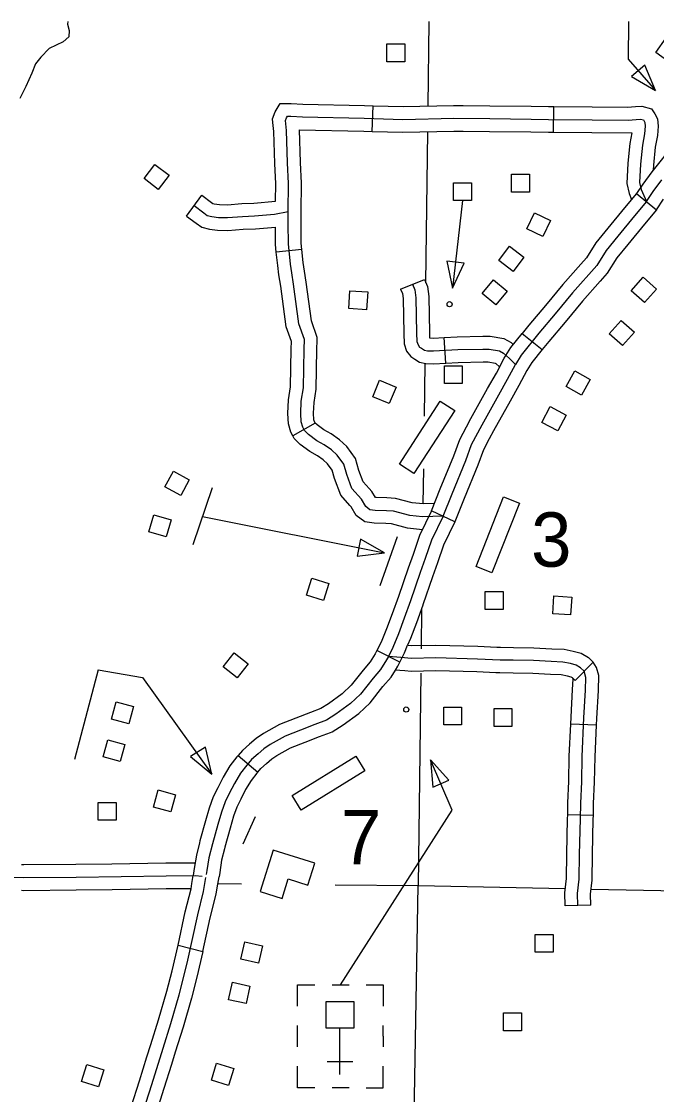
# Model space of a CAD drawing. Extents: x 61396 to 64680, y 55472 to 57605.
# Drawn here: x 63205.3 to 63321.1, y 56489.6 to 56685.3 of the extents above; entities that cross this region are included whole.
import ezdxf

# ---------------------------------------------------------------- set-up
doc = ezdxf.new("R2010")
doc.units = 0
for name, color, linetype in [('31', 7, 'Continuous'), ('32', 7, 'Continuous'), ('35', 7, 'Continuous'), ('45', 7, 'Continuous'), ('5', 7, 'Continuous'), ('56', 7, 'Continuous'), ('57', 7, 'Continuous'), ('58', 7, 'Continuous')]:
    doc.layers.add(name, color=color, linetype=linetype)

msp = doc.modelspace()

# ---------------------------------------------------------------- linework, layer by layer
at = {"layer": '31'}
for p, q in [((63317.45, 56653.93), (63321.06, 56650.95)), ((63296.58, 56628.37), (63300.23, 56625.43)), ((63284.29, 56594.04), (63280.07, 56596.07)), ((63274.29, 56568.45), (63270.1, 56570.55)), ((63309.55, 56568.45), (63306.23, 56565.13)), ((63244.8, 56551.46), (63248.37, 56548.42)), ((63233.85, 56516.86), (63238.39, 56515.68))]:
    msp.add_line(p, q, dxfattribs=at)
for points in [[(63324.79, 56663.59), (63324.33, 56662.98), (63320.26, 56657.86)], [(63320.26, 56657.86), (63318.6, 56655.63), (63317.45, 56653.93)], [(63319.26, 56652.44), (63320.51, 56654.27), (63322.09, 56656.4)], [(63317.45, 56653.93), (63315.28, 56651.3), (63312.22, 56647.59), (63310.02, 56644.91), (63308.33, 56642.19), (63307.31, 56641.04)], [(63319.26, 56652.44), (63317.09, 56649.81), (63314.03, 56646.1), (63311.93, 56643.54), (63310.21, 56640.79), (63305.79, 56635.77), (63302.63, 56631.95), (63299.63, 56628.41), (63296.43, 56624.45), (63295.39, 56622.75)], [(63321.06, 56650.95), (63322.37, 56652.84)], [(63321.06, 56650.95), (63318.89, 56648.32), (63315.84, 56644.62), (63313.84, 56642.17), (63312.1, 56639.38), (63310.83, 56637.94)], [(63307.31, 56641.04), (63304.01, 56637.29), (63300.83, 56633.46), (63297.82, 56629.9), (63296.58, 56628.37)], [(63310.83, 56637.94), (63307.57, 56634.25), (63304.42, 56630.45), (63301.43, 56626.91), (63300.23, 56625.43)], [(63293.31, 56623.85), (63294.52, 56625.81), (63296.58, 56628.37)], [(63300.23, 56625.43), (63298.35, 56623.1), (63297.46, 56621.66)], [(63282.18, 56595.06), (63283.84, 56599.16), (63286.35, 56605.25), (63287.38, 56608.12), (63289.31, 56611.74), (63292.34, 56617.2), (63293.95, 56620.03), (63295.39, 56622.75)], [(63286.46, 56611.38), (63287.26, 56612.87), (63290.3, 56618.35), (63291.9, 56621.16), (63293.31, 56623.85)], [(63297.46, 56621.66), (63296.01, 56618.91), (63294.39, 56616.05), (63291.37, 56610.62), (63290.6, 56609.17)], [(63280.07, 56596.07), (63281.67, 56600.05), (63284.16, 56606.09), (63285.23, 56609.07), (63286.46, 56611.38)], [(63290.6, 56609.17), (63289.53, 56607.17), (63288.54, 56604.4), (63286.01, 56598.27), (63284.29, 56594.04)], [(63280.07, 56596.07), (63277.9, 56591.55), (63276.73, 56588.11), (63275.81, 56585.6), (63274.04, 56580.45)], [(63282.18, 56595.06), (63280.07, 56590.67), (63278.94, 56587.33), (63278.02, 56584.81), (63276.24, 56579.65), (63275.11, 56576.46), (63274.03, 56573.64), (63273, 56571.12), (63272.2, 56569.5)], [(63284.29, 56594.04), (63282.25, 56589.78), (63281.15, 56586.55), (63280.22, 56584.03), (63278.47, 56578.92)], [(63274.04, 56580.45), (63274.03, 56580.42), (63272.91, 56577.27), (63271.85, 56574.5), (63270.87, 56572.09), (63270.1, 56570.55)], [(63278.47, 56578.92), (63278.46, 56578.87), (63277.31, 56575.65), (63276.21, 56572.77), (63275.7, 56571.53)], [(63270.1, 56570.55), (63269.82, 56570), (63268.9, 56568.51), (63267.6, 56567.01), (63265.41, 56564.23), (63263.79, 56562.7), (63261.3, 56560.88), (63259.88, 56559.98)], [(63274.29, 56568.45), (63275.14, 56570.15), (63275.7, 56571.53)], [(63275.7, 56571.53), (63276.5, 56571.46), (63280.87, 56571.57), (63288.51, 56571.35), (63291.95, 56571.21)], [(63291.95, 56571.21), (63292.67, 56571.19), (63295.02, 56571.13), (63298.72, 56571.08), (63302.01, 56570.91), (63304.28, 56570.8), (63305.92, 56570.48), (63307.35, 56570.11), (63308.7, 56569.3), (63309.55, 56568.45)], [(63272.2, 56569.5), (63271.87, 56568.86), (63270.79, 56567.11), (63269.41, 56565.52), (63267.14, 56562.64), (63265.29, 56560.89), (63262.62, 56558.94), (63260.93, 56557.86), (63258.82, 56557.09), (63256.2, 56556.06), (63253.37, 56554.93), (63250.65, 56553.44), (63249.51, 56552.67), (63248.44, 56551.75), (63247.25, 56550.72), (63246.38, 56549.69), (63245.25, 56548.2), (63244.12, 56546.35), (63243.19, 56544.5), (63242.42, 56542.96), (63241.75, 56541.11), (63241.08, 56538.85), (63240.11, 56535.31), (63239.49, 56532.79), (63239.13, 56530.48), (63239.01, 56529.71)], [(63307.89, 56566.79), (63307.24, 56567.44), (63306.43, 56567.93), (63305.4, 56568.2), (63304, 56568.47), (63301.89, 56568.57), (63298.65, 56568.74), (63294.97, 56568.79), (63292.6, 56568.84), (63288.43, 56569.01), (63280.87, 56569.22), (63276.43, 56569.11), (63274.49, 56569.28), (63272.2, 56569.5)], [(63273.49, 56567.02), (63273.92, 56567.72), (63274.29, 56568.45)], [(63273.49, 56567.02), (63273.92, 56567.72), (63274.29, 56568.45)], [(63261.65, 56555.63), (63261.97, 56555.75), (63263.94, 56557.01), (63266.8, 56559.09), (63268.88, 56561.06), (63271.21, 56564.02), (63272.69, 56565.72), (63273.49, 56567.02)], [(63275.18, 56566.87), (63274.28, 56566.94), (63273.49, 56567.02)], [(63291.77, 56566.53), (63288.35, 56566.66), (63280.86, 56566.88), (63276.37, 56566.77), (63275.18, 56566.87)], [(63306.23, 56565.13), (63305.79, 56565.58), (63305.51, 56565.74), (63304.88, 56565.91), (63303.72, 56566.13), (63301.77, 56566.23), (63298.57, 56566.39), (63294.93, 56566.45), (63292.52, 56566.5), (63291.77, 56566.53)], [(63259.88, 56559.98), (63257.99, 56559.28), (63255.33, 56558.24), (63252.37, 56557.06), (63249.42, 56555.45), (63248.09, 56554.54), (63246.9, 56553.52), (63245.58, 56552.37), (63244.8, 56551.46)], [(63248.37, 56548.42), (63248.92, 56549.07), (63249.97, 56549.97), (63250.94, 56550.81), (63251.87, 56551.44), (63254.37, 56552.81), (63257.06, 56553.89), (63259.65, 56554.9), (63261.65, 56555.63)], [(63244.8, 56551.46), (63244.55, 56551.16), (63243.31, 56549.53), (63242.07, 56547.49), (63241.1, 56545.55), (63240.26, 56543.89), (63239.53, 56541.84), (63238.83, 56539.5), (63237.84, 56535.9), (63237.75, 56535.53)], [(63248.37, 56548.42), (63248.21, 56548.23), (63247.19, 56546.88), (63246.17, 56545.22), (63245.29, 56543.46), (63244.58, 56542.04), (63243.98, 56540.38), (63243.34, 56538.21), (63242.38, 56534.72), (63242.3, 56534.42)], [(63237.75, 56535.53), (63237.19, 56533.25), (63236.82, 56530.84), (63236.61, 56529.53)], [(63242.3, 56534.42), (63241.79, 56532.33), (63241.45, 56530.11), (63241.32, 56529.34)], [(63209.63, 56451.04), (63213.02, 56456.19), (63214.77, 56459.22), (63219.03, 56467.64), (63222.37, 56474.73), (63226.28, 56483.88), (63227.52, 56486.55), (63229.06, 56491.43), (63231.11, 56498.06), (63232.55, 56502.58), (63234.04, 56507.82), (63235.53, 56513.58), (63237.44, 56522.36), (63238.51, 56526.63), (63238.92, 56529.16)], [(63236.37, 56528.07), (63236.61, 56529.53)], [(63241, 56527.32), (63241.32, 56529.34)], [(63233.85, 56516.86), (63235.15, 56522.9), (63236.22, 56527.1), (63236.37, 56528.07)], [(63238.39, 56515.68), (63239.72, 56521.83), (63240.81, 56526.15), (63241, 56527.32)], [(63228.17, 56496.47), (63228.88, 56498.76), (63230.31, 56503.26), (63231.78, 56508.44), (63232.76, 56512.2), (63233.85, 56516.86)], [(63238.39, 56515.68), (63237.29, 56511.02), (63236.3, 56507.21), (63234.8, 56501.9), (63233.35, 56497.36), (63232.64, 56495.08)], [(63222.6, 56481.22), (63224.14, 56484.83), (63225.32, 56487.4), (63226.82, 56492.13), (63228.17, 56496.47)], [(63232.64, 56495.08), (63231.29, 56490.73), (63229.71, 56485.7), (63228.42, 56482.93), (63226.91, 56479.38)]]:
    msp.add_lwpolyline(points, dxfattribs=at)
at = {"layer": '32'}
for p, q in [((63274.43, 56636.49), (63278.78, 56638.25)), ((63282.65, 56622.97), (63282.4, 56627.65)), ((63310.13, 56556.94), (63305.44, 56557.14)), ((63309.58, 56540.52), (63304.9, 56540.59)), ((63309.09, 56524.12), (63304.41, 56524.03))]:
    msp.add_line(p, q, dxfattribs=at)
for points in [[(63278.78, 56638.25), (63279.31, 56636.93), (63279.57, 56635.1), (63279.69, 56628.49), (63279.73, 56627.56), (63280.38, 56627.54), (63282.4, 56627.65)], [(63274.43, 56636.49), (63274.75, 56635.7), (63274.89, 56634.73), (63275.01, 56628.36), (63275.08, 56626.5), (63275.5, 56625.18), (63276.27, 56624.17), (63277, 56623.69), (63277.89, 56623.17), (63279.04, 56622.88), (63280.45, 56622.85), (63282.65, 56622.97)], [(63276.6, 56637.37), (63277.03, 56636.31), (63277.23, 56634.91), (63277.35, 56628.42), (63277.41, 56626.91), (63277.61, 56626.28), (63277.89, 56625.91), (63278.24, 56625.68), (63278.78, 56625.36), (63279.35, 56625.22), (63280.42, 56625.19), (63284.85, 56625.43), (63289.44, 56625.53), (63290.58, 56625.53), (63292.44, 56625.24), (63293.18, 56624.81), (63294.28, 56623.81), (63295.39, 56622.75)], [(63282.4, 56627.65), (63284.77, 56627.78), (63289.41, 56627.87), (63290.76, 56627.87), (63293.24, 56627.49), (63294.58, 56626.71), (63294.96, 56626.36)], [(63282.65, 56622.97), (63284.94, 56623.09), (63289.46, 56623.19), (63290.4, 56623.19), (63291.65, 56622.99), (63291.79, 56622.91), (63292.49, 56622.28)], [(63310.13, 56556.94), (63310.18, 56558.19), (63310.49, 56563.26), (63310.59, 56565.99), (63310.13, 56567.48), (63309.55, 56568.45)], [(63306.75, 56524.07), (63306.71, 56526.25), (63307.01, 56528.87), (63307.05, 56533.41), (63307.23, 56539.86), (63307.27, 56542.74), (63307.45, 56546.62), (63307.54, 56551.25), (63307.84, 56558.31), (63308.15, 56563.37), (63308.23, 56565.68), (63307.89, 56566.79)], [(63305.44, 56557.14), (63305.5, 56558.43), (63305.8, 56563.49), (63305.88, 56565.37), (63305.82, 56565.54)], [(63304.9, 56540.59), (63304.93, 56542.81), (63305.1, 56546.7), (63305.19, 56551.32), (63305.44, 56557.14)], [(63309.58, 56540.52), (63309.62, 56542.67), (63309.79, 56546.55), (63309.88, 56551.17), (63310.13, 56556.94)], [(63304.41, 56524.03), (63304.36, 56526.37), (63304.67, 56529.02), (63304.71, 56533.45), (63304.89, 56539.91), (63304.9, 56540.59)], [(63309.09, 56524.12), (63309.05, 56526.14), (63309.35, 56528.72), (63309.4, 56533.36), (63309.57, 56539.81), (63309.58, 56540.52)]]:
    msp.add_lwpolyline(points, dxfattribs=at)
at = {"layer": '35'}
msp.add_lwpolyline([(63213.73, 56685.27), (63213.68, 56684.76), (63214, 56683.6), (63213.92, 56682.44), (63212.93, 56681.53), (63210.38, 56680.34), (63208.84, 56678.76), (63207.85, 56677.53), (63207.18, 56675.83), (63206.11, 56673.41), (63204.98, 56671.2)], dxfattribs=at)
at = {"layer": '45'}
for p, q in [((63269.27, 56665.23), (63269.41, 56669.91)), ((63302.32, 56665.06), (63302.35, 56669.74)), ((63235.39, 56649.8), (63238.17, 56653.58)), ((63256.44, 56643.68), (63251.77, 56643.22)), ((63258.84, 56612.03), (63254.77, 56609.71))]:
    msp.add_line(p, q, dxfattribs=at)
for points in [[(63251.13, 56666.84), (63251.05, 56667.52), (63251.55, 56668.77), (63252.48, 56670.32), (63254.49, 56670.32), (63256.61, 56670.22), (63267.87, 56669.96), (63269.41, 56669.91)], [(63269.41, 56669.91), (63274.87, 56669.75), (63284.09, 56669.96), (63285.85, 56669.95)], [(63285.85, 56669.95), (63290.71, 56669.91), (63298.25, 56669.8), (63301.42, 56669.75), (63302.35, 56669.74)], [(63302.35, 56669.74), (63309.36, 56669.7), (63315.83, 56669.63), (63317.25, 56669.76), (63318.39, 56669.81), (63320.2, 56669.36), (63320.76, 56668.43)], [(63253.96, 56650.62), (63254.02, 56655.71), (63253.81, 56659.47), (63253.65, 56665.37), (63253.44, 56667.2), (63253.65, 56667.72), (63253.81, 56667.98), (63254.44, 56667.98), (63256.53, 56667.88), (63267.81, 56667.62), (63274.86, 56667.41), (63284.11, 56667.62), (63290.69, 56667.56), (63298.21, 56667.46), (63301.4, 56667.41), (63309.34, 56667.35), (63315.92, 56667.29), (63317.41, 56667.42), (63318.15, 56667.46), (63318.69, 56667.32), (63318.99, 56666.82), (63319.03, 56666.21), (63318.93, 56664.76), (63318.52, 56662.7), (63318.18, 56659.26), (63318.01, 56655.92), (63318.32, 56654.64), (63319.26, 56652.44)], [(63320.76, 56668.43), (63321.3, 56667.53), (63321.38, 56666.19), (63321.25, 56664.45), (63320.84, 56662.36), (63320.52, 56659.09), (63320.47, 56658.16)], [(63251.64, 56652.5), (63251.67, 56655.66), (63251.47, 56659.37), (63251.31, 56665.21), (63251.13, 56666.84)], [(63256.3, 56650.59), (63256.36, 56655.76), (63256.15, 56659.57), (63255.99, 56665.54)], [(63255.99, 56665.54), (63267.75, 56665.27), (63269.27, 56665.23)], [(63269.27, 56665.23), (63274.85, 56665.06), (63284.12, 56665.27), (63285.82, 56665.26)], [(63285.82, 56665.26), (63290.66, 56665.22), (63298.18, 56665.12), (63301.37, 56665.06), (63302.32, 56665.06)], [(63302.32, 56665.06), (63309.32, 56665.01), (63316.57, 56664.94)], [(63316.57, 56664.94), (63316.2, 56663.04), (63315.85, 56659.43), (63315.66, 56655.71), (63316.08, 56653.91), (63316.54, 56652.83)], [(63238.17, 56653.58), (63239.95, 56652.27), (63240.21, 56652.07), (63240.46, 56652.01), (63241.41, 56651.89), (63242.84, 56651.84), (63245.46, 56652.05), (63247.65, 56652.15), (63251.64, 56652.5)], [(63236.78, 56651.69), (63238.56, 56650.38), (63239.18, 56649.92), (63240.02, 56649.71), (63241.22, 56649.55), (63242.89, 56649.5), (63245.61, 56649.71), (63247.8, 56649.81), (63251.41, 56650.12), (63253.96, 56650.62)], [(63282.18, 56595.06), (63278.44, 56594.95), (63276.11, 56595.21), (63273.13, 56595.99), (63271.83, 56596.07), (63269.8, 56596.12), (63268.85, 56596.24), (63268.11, 56596.81), (63267.29, 56598.15), (63265.56, 56600.13), (63264.61, 56602.68), (63264.1, 56604.54), (63262.84, 56606.18), (63261.81, 56607.17), (63260.51, 56608.08), (63259.17, 56608.81), (63257.66, 56609.94), (63256.92, 56610.67), (63256.58, 56611.28), (63256.32, 56612.27), (63256.23, 56613.82), (63256.32, 56616.03), (63256.71, 56618.45), (63256.84, 56625.53), (63256.88, 56627.26), (63255.87, 56630.12), (63254.92, 56637.36), (63254.57, 56639.42), (63254.35, 56641.03), (63253.98, 56644.74), (63253.96, 56648.36), (63253.96, 56650.62)], [(63256.44, 56643.68), (63256.32, 56644.86), (63256.3, 56648.37), (63256.3, 56650.62)], [(63235.39, 56649.8), (63237.16, 56648.5), (63238.16, 56647.76), (63239.58, 56647.4), (63241.03, 56647.21), (63242.95, 56647.15), (63245.75, 56647.37), (63247.96, 56647.47), (63251.62, 56647.79)], [(63251.77, 56643.22), (63251.64, 56644.62), (63251.62, 56647.79)], [(63254.53, 56626.89), (63253.58, 56629.57), (63252.61, 56637.01), (63252.25, 56639.06), (63252.02, 56640.76), (63251.77, 56643.22)], [(63259.22, 56627.18), (63259.23, 56627.63), (63258.17, 56630.67), (63257.24, 56637.71), (63256.89, 56639.77), (63256.68, 56641.31), (63256.44, 56643.68)], [(63254.77, 56609.71), (63254.39, 56610.38), (63253.99, 56611.9), (63253.88, 56613.81), (63253.98, 56616.26), (63254.37, 56618.65), (63254.49, 56625.58), (63254.53, 56626.89)], [(63258.84, 56612.03), (63258.77, 56612.17), (63258.64, 56612.63), (63258.58, 56613.84), (63258.65, 56615.79), (63259.05, 56618.24), (63259.18, 56625.48), (63259.22, 56627.18)], [(63268.7, 56600.1), (63267.61, 56601.35), (63266.84, 56603.41), (63266.23, 56605.6), (63264.6, 56607.75), (63263.3, 56608.99), (63261.75, 56610.07), (63260.44, 56610.79), (63259.19, 56611.72), (63258.8, 56612.11), (63258.84, 56612.03)], [(63265.17, 56597.02), (63263.52, 56598.91), (63262.38, 56601.95), (63261.96, 56603.47), (63261.09, 56604.61), (63260.31, 56605.36), (63259.27, 56606.09), (63257.9, 56606.84), (63256.12, 56608.16), (63255.04, 56609.24), (63254.77, 56609.71)], [(63280.58, 56597.36), (63278.54, 56597.3), (63276.54, 56597.52), (63273.5, 56598.31), (63271.93, 56598.41), (63269.98, 56598.46), (63269.84, 56598.48), (63269.19, 56599.54), (63268.7, 56600.1)], [(63278.4, 56592.6), (63275.68, 56592.9), (63272.75, 56593.66), (63271.73, 56593.73), (63269.62, 56593.77), (63267.92, 56594.01), (63266.34, 56595.21), (63265.4, 56596.75), (63265.17, 56597.02)], [(63221.75, 56531.64), (63215.24, 56531.54), (63205.73, 56531.47), (63205.3, 56531.47)], [(63236.97, 56531.82), (63231.64, 56531.79), (63221.75, 56531.64)], [(63238.28, 56529.37), (63236.99, 56529.48), (63231.66, 56529.44), (63215.26, 56529.2), (63205.73, 56529.13), (63191.28, 56529.2)], [(63221.82, 56526.95), (63215.29, 56526.85), (63205.73, 56526.78), (63205.28, 56526.79)], [(63236.22, 56527.13), (63231.69, 56527.1), (63221.82, 56526.95)]]:
    msp.add_lwpolyline(points, dxfattribs=at)
at = {"layer": '5'}
for points in [[(63279.59, 56685.27), (63279.4, 56669.85)], [(63279.34, 56665.16), (63279, 56637.59)], [(63278.82, 56622.89), (63278.7, 56613.31)], [(63278.58, 56603.73), (63278.5, 56597.3)], [(63278.26, 56578.31), (63278.17, 56570.86)], [(63278.11, 56566.42), (63277.63, 56527.7)], [(63241.12, 56528.1), (63245.43, 56528.05)], [(63262.53, 56527.86), (63277.63, 56527.7)], [(63276.4, 56457.67), (63277.63, 56527.7)], [(63277.63, 56527.7), (63304.45, 56527.17)], [(63309.16, 56527.08), (63417.27, 56524.98)]]:
    msp.add_lwpolyline(points, dxfattribs=at)
at = {"layer": '56'}
for points in [[(63315.99, 56685.27), (63315.94, 56678.38), (63320.91, 56672.68)], [(63285.73, 56652.61), (63283.91, 56636.64)], [(63240.09, 56600.23), (63236.55, 56589.83)], [(63238.32, 56595.03), (63271.51, 56588.37)], [(63273.8, 56591.29), (63270.67, 56582.34)], [(63219.26, 56567.06), (63214.96, 56550.69)], [(63219.26, 56567.06), (63227.36, 56565.66), (63240.02, 56548.06)], [(63247.89, 56540.25), (63245.64, 56535.28)]]:
    msp.add_lwpolyline(points, dxfattribs=at)
for points in [[(63320.94, 56679.62), (63322.83, 56682.27), (63325.48, 56680.37), (63323.59, 56677.72)], [(63271.94, 56677.93), (63271.94, 56681.18), (63275.2, 56681.18), (63275.2, 56677.93)], [(63318.97, 56677.33), (63316.56, 56675.23), (63320.91, 56672.68)], [(63227.66, 56656.63), (63229.63, 56659.21), (63232.22, 56657.23), (63230.25, 56654.65)], [(63284.1, 56652.61), (63284.1, 56655.87), (63287.36, 56655.87), (63287.36, 56652.61)], [(63294.67, 56654.15), (63294.67, 56657.4), (63297.93, 56657.4), (63297.93, 56654.15)], [(63297.44, 56647.46), (63298.84, 56650.4), (63301.78, 56649), (63300.39, 56646.06)], [(63292.34, 56641.68), (63294.31, 56644.27), (63296.91, 56642.3), (63294.94, 56639.71)], [(63286.04, 56641.21), (63282.87, 56641.57), (63283.91, 56636.64)], [(63318.93, 56634.03), (63316.49, 56636.18), (63318.64, 56638.63), (63321.08, 56636.48)], [(63289.28, 56635.67), (63291.35, 56638.18), (63293.87, 56636.11), (63291.8, 56633.6)], [(63264.97, 56632.94), (63265.2, 56636.18), (63268.45, 56635.95), (63268.22, 56632.7)], [(63314.89, 56626.17), (63312.46, 56628.33), (63314.63, 56630.77), (63317.06, 56628.6)], [(63282.42, 56619.24), (63282.42, 56622.5), (63285.68, 56622.5), (63285.68, 56619.24)], [(63304.59, 56618.7), (63306.17, 56621.54), (63309.02, 56619.96), (63307.44, 56617.11)], [(63269.34, 56616.83), (63270.57, 56619.84), (63273.6, 56618.61), (63272.37, 56615.6)], [(63281.66, 56616.01), (63284.29, 56614.31), (63276.85, 56602.84), (63274.23, 56604.54)], [(63300.2, 56612.16), (63301.72, 56615.04), (63304.6, 56613.51), (63303.08, 56610.64)], [(63231.47, 56600.42), (63233.03, 56603.28), (63235.9, 56601.71), (63234.34, 56598.86)], [(63293.22, 56598.61), (63296.13, 56597.45), (63291.08, 56584.75), (63288.18, 56585.9)], [(63228.53, 56592.22), (63229.45, 56595.34), (63232.58, 56594.42), (63231.66, 56591.3)], [(63267.13, 56590.88), (63266.51, 56587.75), (63271.51, 56588.37)], [(63257.25, 56580.67), (63258.24, 56583.77), (63261.34, 56582.78), (63260.36, 56579.68)], [(63289.86, 56578.08), (63289.86, 56581.33), (63293.13, 56581.33), (63293.13, 56578.08)], [(63302.17, 56577.29), (63302.38, 56580.53), (63305.63, 56580.33), (63305.43, 56577.08)], [(63242.05, 56567.59), (63244.06, 56570.15), (63246.63, 56568.14), (63244.62, 56565.58)], [(63221.71, 56558.06), (63222.57, 56561.2), (63225.72, 56560.34), (63224.86, 56557.2)], [(63282.29, 56557.01), (63282.29, 56560.26), (63285.55, 56560.26), (63285.55, 56557.01)], [(63291.47, 56556.74), (63291.47, 56560), (63294.73, 56560), (63294.73, 56556.74)], [(63223.31, 56550.31), (63220.17, 56551.17), (63221.03, 56554.32), (63224.17, 56553.46)], [(63238.85, 56552.96), (63236.14, 56551.28), (63240.02, 56548.06)], [(63266.26, 56551.32), (63267.9, 56548.66), (63256.28, 56541.46), (63254.63, 56544.12)], [(63229.36, 56542.02), (63230.23, 56545.16), (63233.38, 56544.29), (63232.51, 56541.15)], [(63219.29, 56539.62), (63219.29, 56542.87), (63222.55, 56542.87), (63222.55, 56539.62)], [(63245.33, 56514.28), (63246.05, 56517.45), (63249.24, 56516.72), (63248.51, 56513.55)], [(63298.98, 56515.56), (63298.98, 56518.81), (63302.24, 56518.81), (63302.24, 56515.56)], [(63243.08, 56506.9), (63243.76, 56510.08), (63246.95, 56509.4), (63246.27, 56506.22)], [(63293.21, 56501.23), (63293.21, 56504.49), (63296.47, 56504.49), (63296.47, 56501.23)], [(63216.23, 56492.02), (63217.23, 56495.12), (63220.33, 56494.12), (63219.34, 56491.03)], [(63239.95, 56492.22), (63240.89, 56495.34), (63244.01, 56494.39), (63243.07, 56491.28)]]:
    msp.add_lwpolyline(points, close=True, dxfattribs=at)
msp.add_circle((63283.36, 56633.72), 0.469, dxfattribs=at)
at = {"layer": '57'}
for p, q in [((63261.93, 56509.61), (63265.05, 56509.61)), ((63255.66, 56498.31), (63255.66, 56502.22)), ((63263.38, 56493.28), (63263.38, 56501.7)), ((63271.28, 56500.23), (63271.28, 56502.22)), ((63271.28, 56500.23), (63271.28, 56498.31)), ((63261.03, 56495.63), (63265.72, 56495.63)), ((63265.05, 56490.86), (63261.93, 56490.86))]:
    msp.add_line(p, q, dxfattribs=at)
for points in [[(63263.49, 56509.61), (63283.86, 56541.46), (63279.89, 56550.66)], [(63255.66, 56505.7), (63255.66, 56509.61), (63258.78, 56509.61)], [(63268.16, 56509.61), (63271.28, 56509.61), (63271.28, 56505.7)], [(63258.78, 56490.86), (63255.66, 56490.86), (63255.66, 56494.77)], [(63268.16, 56490.86), (63271.28, 56490.86), (63271.28, 56494.77)]]:
    msp.add_lwpolyline(points, dxfattribs=at)
for points in [[(63280.32, 56545.64), (63283.25, 56546.91), (63279.89, 56550.66)], [(63265.9, 56506.57), (63265.9, 56501.7), (63260.84, 56501.7), (63260.84, 56506.57)]]:
    msp.add_lwpolyline(points, close=True, dxfattribs=at)
msp.add_circle((63275.46, 56559.81), 0.469, dxfattribs=at)
at = {"layer": '58'}
msp.add_lwpolyline([(63251.21, 56534.19), (63248.83, 56526.62), (63252.82, 56525.36), (63253.95, 56528.94), (63257.53, 56527.82), (63258.78, 56531.81)], close=True, dxfattribs=at)

# ---------------------------------------------------------------- texts
at = {"layer": '56'}
for s, p in [('3', (63298.22, 56585.86)), ('7', (63263.53, 56531.57))]:
    msp.add_text(s, height=9.9, dxfattribs=at).set_placement(p)

doc.saveas('drawing.dxf')
